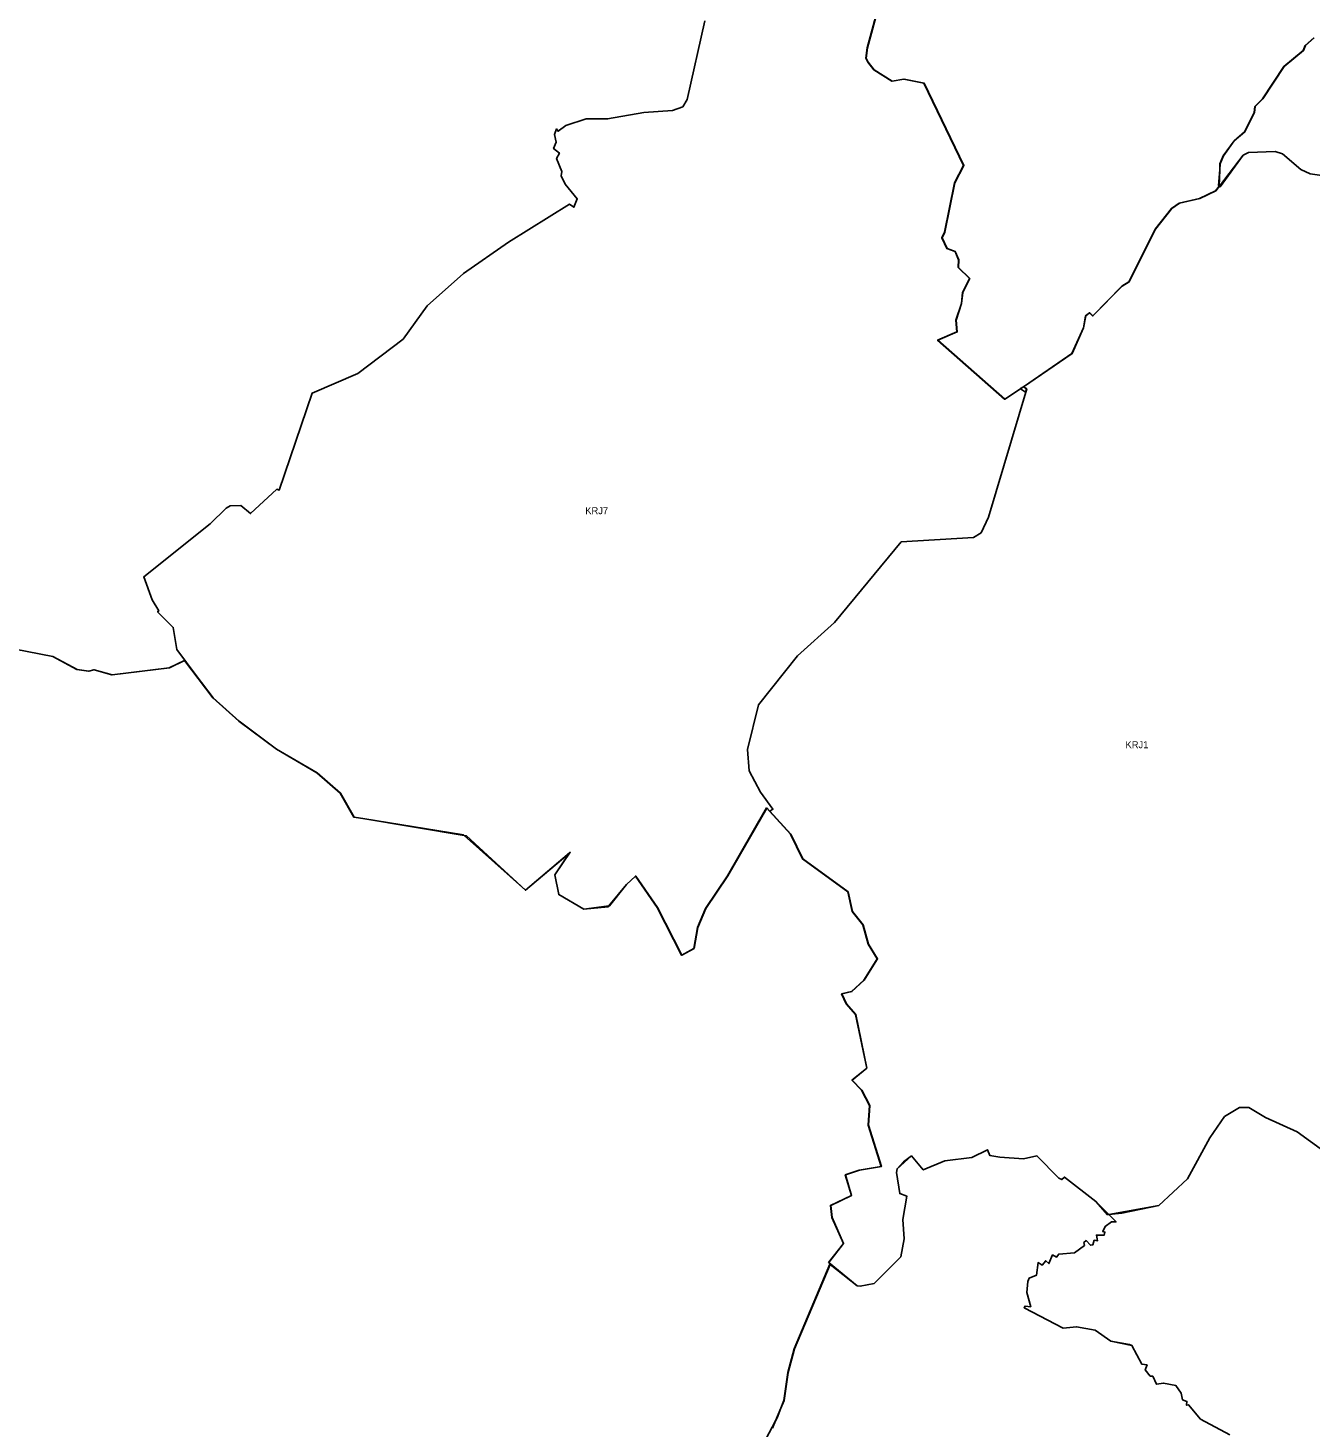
# Model space of a CAD drawing. Extents: x -563112 to -465432, y -1206259 to -1132144.
# Drawn here: x -539574 to -530418, y -1182339 to -1172346 of the extents above; entities that cross this region are included whole.
import ezdxf

# ---------------------------------------------------------------- set-up
doc = ezdxf.new("R2010")
doc.units = 0
doc.layers.add('krajiny', color=7, linetype='Continuous')

msp = doc.modelspace()

# ---------------------------------------------------------------- linework, layer by layer
at = {"layer": 'krajiny'}
for points in [[(-533496.29, -1172164.7), (-533582.38, -1172486.33), (-533593.54, -1172560.47), (-533577.95, -1172590.58), (-533536.6, -1172645.2), (-533407.61, -1172725.48), (-533407.16, -1172725.76), (-533322.96, -1172711.66), (-533321.84, -1172711.47), (-533178.98, -1172738.78), (-532895.06, -1173328.04), (-532960.37, -1173450.05), (-533030.69, -1173803.37), (-533050.53, -1173844.81), (-533015.18, -1173919.49), (-532956.36, -1173940.86), (-532930.99, -1174001.57), (-532934.1, -1174054.49), (-532852.91, -1174134.4), (-532902.3, -1174234.56), (-532911.29, -1174312.58), (-532951.23, -1174431.18), (-532943.05, -1174515.41), (-533080.59, -1174574.89), (-532603.12, -1174994.46), (-532602.21, -1174995.26), (-532490.08, -1174920.45), (-532469.9, -1174906.99), (-532468.82, -1174906.27), (-532446.67, -1174921.9), (-532720.12, -1175837.22), (-532773.04, -1175949.73), (-532825.97, -1175982.82), (-533342.02, -1176013.25), (-533818.38, -1176589.04), (-534083.02, -1176827.29), (-534360.9, -1177178.06), (-534440.29, -1177495.74), (-534427.06, -1177647.95), (-534347.66, -1177800.17), (-534257.89, -1177922.16), (-534280.36, -1177935.65), (-534281.74, -1177936.48), (-534301.94, -1177914.15), (-534303.23, -1177912.72), (-534582.94, -1178397.76), (-534739.65, -1178630.56), (-534797.31, -1178766.3), (-534823.47, -1178916.07), (-534907.83, -1178963.96), (-534909.47, -1178964.89), (-535085.15, -1178623.98), (-535238.69, -1178400.49), (-535239.51, -1178399.3), (-535302.29, -1178458.82), (-535428.49, -1178611.92), (-535433.59, -1178618.1), (-535608.67, -1178636.04), (-535787.02, -1178531.1), (-535815.49, -1178390.49), (-535704.02, -1178229.67), (-535708.88, -1178233.78), (-536024.47, -1178500.17), (-536461.72, -1178110.06), (-536467.3, -1178105.08), (-537185.65, -1177989.67), (-537248.15, -1177979.63), (-537347.39, -1177807.56), (-537512.79, -1177661.96), (-537802.18, -1177493.63), (-538069.5, -1177293.8), (-538256.01, -1177127.53), (-538373.79, -1176968.85), (-538512.44, -1176782.04), (-538538.13, -1176625.03), (-538649.94, -1176512.61), (-538641.29, -1176506.22), (-538689.34, -1176427.85), (-538748.49, -1176262.91), (-538275.3, -1175886.06), (-538159.29, -1175774.39), (-538132.31, -1175757.52), (-538056.31, -1175754.35), (-537986.07, -1175811.81), (-537797.85, -1175638.22), (-537780.87, -1175644.05), (-537545.87, -1174951.77), (-537221.68, -1174812.78), (-536897.5, -1174567.91), (-536725.48, -1174329.65), (-536467.46, -1174098.02), (-536145.91, -1173875.63), (-535709.25, -1173604.28), (-535677.85, -1173625.27), (-535654.14, -1173565.4), (-535740.33, -1173461.12), (-535769.03, -1173401.76), (-535763.8, -1173370.51), (-535802.49, -1173277.42), (-535781.34, -1173238.14), (-535823.23, -1173206.61), (-535804.28, -1173159.88), (-535816.58, -1173105.94), (-535803.59, -1173066.15), (-535790.87, -1173083.11), (-535735.71, -1173041.73), (-535590.16, -1172995.4), (-535437.99, -1172995.4), (-535179.97, -1172949.07), (-534974.87, -1172935.84), (-534902.09, -1172909.36), (-534869.01, -1172856.42), (-534743.31, -1172293.87)], [(-530396.76, -1172416.91), (-530459.25, -1172470.54), (-530473.52, -1172506.43), (-530611.64, -1172619.68), (-530763, -1172850.86), (-530817.71, -1172906.59), (-530823.96, -1172948.13), (-530893.41, -1173086.05), (-530967.3, -1173152.14), (-531043.86, -1173259.18), (-531068.49, -1173315.57), (-531069.56, -1173357.23), (-531072.56, -1173473.8), (-531072.6, -1173475.25), (-531099.02, -1173508.23), (-531213.42, -1173562.4), (-531358.21, -1173595.39), (-531412.88, -1173633.77), (-531529.66, -1173781.62), (-531717.24, -1174158.26), (-531768.67, -1174188.23), (-531975.54, -1174399.98), (-531976.59, -1174401.06), (-531997.91, -1174379.06), (-531998.81, -1174378.13), (-532026.46, -1174399.42), (-532042.56, -1174484.99), (-532124.2, -1174668.52), (-532470.92, -1174906.27), (-532603.12, -1174994.46), (-532604.31, -1174995.26), (-533082.69, -1174574.89), (-532945.15, -1174515.41), (-532953.33, -1174431.18), (-532913.39, -1174312.58), (-532904.4, -1174234.56), (-532855.01, -1174134.4), (-532936.2, -1174054.49), (-532933.09, -1174001.57), (-532958.46, -1173940.86), (-533017.28, -1173919.49), (-533052.63, -1173844.81), (-533032.79, -1173803.37), (-532962.47, -1173450.05), (-532897.16, -1173328.04), (-533181.08, -1172738.78), (-533322.96, -1172711.66), (-533323.94, -1172711.47), (-533407.61, -1172725.48), (-533409.26, -1172725.76), (-533538.7, -1172645.2), (-533580.05, -1172590.58), (-533595.64, -1172560.47), (-533584.48, -1172486.33), (-533498.39, -1172164.7)], [(-534743.31, -1172293.87), (-534869.01, -1172856.42), (-534902.09, -1172909.36), (-534974.87, -1172935.84), (-535179.97, -1172949.07), (-535437.99, -1172995.4), (-535590.16, -1172995.4), (-535735.71, -1173041.73), (-535790.87, -1173083.11), (-535803.59, -1173066.15), (-535816.58, -1173105.94), (-535804.28, -1173159.88), (-535823.23, -1173206.61), (-535781.34, -1173238.14), (-535802.49, -1173277.42), (-535763.8, -1173370.51), (-535769.03, -1173401.76), (-535740.33, -1173461.12), (-535654.14, -1173565.4), (-535677.85, -1173625.27), (-535709.25, -1173604.28), (-536145.91, -1173875.63), (-536467.46, -1174098.02), (-536725.48, -1174329.65), (-536897.5, -1174567.91), (-537221.68, -1174812.78), (-537545.87, -1174951.77), (-537780.87, -1175644.05), (-537797.85, -1175638.22), (-537986.07, -1175811.81), (-538056.31, -1175754.35), (-538132.31, -1175757.52), (-538159.29, -1175774.39), (-538275.3, -1175886.06), (-538748.49, -1176262.91), (-538689.34, -1176427.85), (-538641.29, -1176506.22), (-538649.94, -1176512.61), (-538538.13, -1176625.03), (-538512.44, -1176782.04), (-538373.79, -1176968.85), (-538256.01, -1177127.53), (-538456.81, -1176861.77), (-538457.38, -1176861.02), (-538566.4, -1176913.61), (-538974.53, -1176962.69), (-538976, -1176962.87), (-539103.34, -1176927.89), (-539104.39, -1176927.6), (-539141.5, -1176937.63), (-539142.25, -1176937.83), (-539225.52, -1176925.54), (-539398.31, -1176832.3), (-539764.72, -1176761.4)], [(-530272.31, -1173407.97), (-530423.14, -1173386.86), (-530491, -1173354.76), (-530620.87, -1173244.01), (-530673.46, -1173228.53), (-530863.69, -1173233.82), (-530902.1, -1173253.92), (-531065.26, -1173478.94), (-531071.25, -1173474.72), (-531072.56, -1173473.8), (-531078.14, -1173469.88), (-531069.56, -1173357.23), (-531066.39, -1173315.57), (-531041.76, -1173259.18), (-530965.2, -1173152.14), (-530891.31, -1173086.05), (-530821.86, -1172948.13), (-530815.61, -1172906.59), (-530760.9, -1172850.86), (-530609.54, -1172619.68), (-530471.42, -1172506.43), (-530457.15, -1172470.54), (-530394.66, -1172416.91)], [(-530327.09, -1180362.66), (-530516.91, -1180224.5), (-530743, -1180123.28), (-530862.33, -1180050.34), (-530928.49, -1180050.34), (-531034.34, -1180116.52), (-531140.2, -1180268.74), (-531298.99, -1180559.94), (-531504.08, -1180751.87), (-531768.72, -1180804.82), (-531860.34, -1180815.65), (-531860.43, -1180815.66), (-531869.44, -1180816.73), (-531952.44, -1180723.29), (-532176.3, -1180547.65), (-532197.31, -1180565.38), (-532216.59, -1180554.66), (-532374.07, -1180396.27), (-532468.61, -1180417.07), (-532637.56, -1180405.08), (-532708.93, -1180394.28), (-532725.86, -1180353.27), (-532839.03, -1180409.28), (-533030.29, -1180432.1), (-533185.59, -1180497.42), (-533269.39, -1180397.38), (-533372.51, -1180488.07), (-533376.27, -1180515.8), (-533352.92, -1180665.71), (-533302.29, -1180684.74), (-533329.83, -1180851.46), (-533321.13, -1180989.7), (-533346.22, -1181118.47), (-533535.29, -1181306.76), (-533636.25, -1181325.56), (-533655.99, -1181324.07), (-533855.9, -1181161.17), (-533860.35, -1181157.55), (-533755.43, -1181023.28), (-533837.2, -1180835.67), (-533847.93, -1180749.81), (-533698.5, -1180679.29), (-533742.41, -1180533.05), (-533643.46, -1180497.63), (-533486.1, -1180472.89), (-533579.04, -1180178.48), (-533568.85, -1180036.52), (-533625.06, -1179926.67), (-533694.81, -1179857.46), (-533589.02, -1179769.72), (-533668.89, -1179388.16), (-533735.68, -1179310.71), (-533768.68, -1179240.41), (-533696.19, -1179224.08), (-533608.63, -1179142.07), (-533513.26, -1178990.53), (-533578.18, -1178886.42), (-533616.62, -1178748.47), (-533692.15, -1178653.52), (-533723.36, -1178511.12), (-534047.8, -1178277.04), (-534132.58, -1178101.37), (-534281.74, -1177936.48), (-534280.36, -1177935.65), (-534257.89, -1177922.16), (-534347.66, -1177800.17), (-534427.06, -1177647.95), (-534440.29, -1177495.74), (-534360.9, -1177178.06), (-534083.02, -1176827.29), (-533818.38, -1176589.04), (-533342.02, -1176013.25), (-532825.97, -1175982.82), (-532773.04, -1175949.73), (-532720.12, -1175837.22), (-532446.67, -1174921.9), (-532468.82, -1174906.27), (-532122.1, -1174668.52), (-532040.46, -1174484.99), (-532024.36, -1174399.42), (-531997.91, -1174379.06), (-531996.71, -1174378.13), (-531975.54, -1174399.98), (-531974.49, -1174401.06), (-531766.57, -1174188.23), (-531715.14, -1174158.26), (-531527.56, -1173781.62), (-531410.78, -1173633.77), (-531356.11, -1173595.39), (-531211.32, -1173562.4), (-531096.92, -1173508.23), (-531071.25, -1173474.72), (-530902.1, -1173253.92), (-530863.69, -1173233.82), (-530673.46, -1173228.53), (-530620.87, -1173244.01), (-530491, -1173354.76), (-530423.14, -1173386.86), (-530272.31, -1173407.97)], [(-539764.62, -1176761.01), (-539396.19, -1176832.3), (-539223.4, -1176925.54), (-539141.5, -1176937.63), (-539140.13, -1176937.83), (-539103.34, -1176927.89), (-539102.27, -1176927.6), (-538974.53, -1176962.69), (-538973.88, -1176962.87), (-538564.28, -1176913.61), (-538456.81, -1176861.77), (-538455.26, -1176861.02), (-538373.79, -1176968.85), (-538253.89, -1177127.53), (-538067.38, -1177293.8), (-537800.06, -1177493.63), (-537510.67, -1177661.96), (-537345.27, -1177807.56), (-537246.03, -1177979.63), (-537185.65, -1177989.67), (-536461.72, -1178110.06), (-536444.46, -1178112.93), (-536024.47, -1178500.17), (-535708.22, -1178232.8), (-535708.88, -1178233.78), (-535815.49, -1178390.49), (-535787.02, -1178531.1), (-535608.67, -1178636.04), (-535428.49, -1178611.92), (-535424.26, -1178611.35), (-535302.29, -1178458.82), (-535238.69, -1178400.49), (-535237.39, -1178399.3), (-535083.03, -1178623.98), (-534907.83, -1178963.96), (-534907.35, -1178964.89), (-534821.35, -1178916.07), (-534795.19, -1178766.3), (-534737.53, -1178630.56), (-534580.82, -1178397.76), (-534301.94, -1177914.15), (-534301.11, -1177912.72), (-534280.36, -1177935.65), (-534130.46, -1178101.37), (-534045.68, -1178277.04), (-533721.24, -1178511.12), (-533690.03, -1178653.52), (-533614.5, -1178748.47), (-533576.06, -1178886.42), (-533511.14, -1178990.53), (-533606.51, -1179142.07), (-533694.07, -1179224.08), (-533766.56, -1179240.41), (-533733.56, -1179310.71), (-533666.77, -1179388.16), (-533586.9, -1179769.72), (-533692.69, -1179857.46), (-533622.94, -1179926.67), (-533566.73, -1180036.52), (-533576.92, -1180178.48), (-533483.98, -1180472.89), (-533641.34, -1180497.63), (-533740.29, -1180533.05), (-533696.38, -1180679.29), (-533845.81, -1180749.81), (-533835.08, -1180835.67), (-533753.31, -1181023.28), (-533858.23, -1181157.55), (-533855.9, -1181161.17), (-533850.02, -1181170.33), (-533850.54, -1181171.58), (-534103.2, -1181773.79), (-534149.46, -1181942.87), (-534178.77, -1182141.91), (-534202.01, -1182198.34), (-534239.21, -1182288.71), (-534260.54, -1182340.51)], [(-530998.07, -1182386.92), (-531206.52, -1182277.22), (-531292.02, -1182172.78), (-531305.83, -1182176.6), (-531303.71, -1182149.84), (-531334.4, -1182139.24), (-531343.44, -1182091.42), (-531381.99, -1182035.8), (-531471.03, -1182018.49), (-531521.58, -1182027.08), (-531547.13, -1181969.7), (-531565.47, -1181968.36), (-531600.94, -1181923.93), (-531587.59, -1181888.65), (-531626.11, -1181882.78), (-531695.75, -1181750.79), (-531847, -1181719), (-531958.01, -1181641.18), (-532090.59, -1181616.22), (-532186.28, -1181627.14), (-532465.16, -1181481.07), (-532459, -1181468.57), (-532417.47, -1181473.27), (-532446.55, -1181373.12), (-532438.46, -1181292.59), (-532430.46, -1181269.42), (-532377.75, -1181248.82), (-532365.91, -1181158.04), (-532336.11, -1181175.84), (-532310.7, -1181144.76), (-532288.79, -1181165.42), (-532262.04, -1181103.5), (-532234.24, -1181119.19), (-532217.86, -1181098.27), (-532106.15, -1181087.8), (-532034.91, -1181035.54), (-532038.39, -1181015.15), (-532022.61, -1181001.73), (-531991.06, -1181034.72), (-531973.95, -1181031.5), (-531964.56, -1180998.92), (-531941.03, -1181002.58), (-531948.94, -1180961.87), (-531894.78, -1180963.5), (-531888.48, -1180940.51), (-531903.89, -1180935.42), (-531886.19, -1180899.9), (-531840.89, -1180868.45), (-531808.78, -1180867.52), (-531860.43, -1180815.67), (-531860.34, -1180815.65), (-531504.08, -1180751.87), (-531298.99, -1180559.94), (-531140.2, -1180268.74), (-531034.34, -1180116.52), (-530928.49, -1180050.34), (-530862.33, -1180050.34), (-530743, -1180123.28), (-530516.91, -1180224.5), (-530327.09, -1180362.66)], [(-534308, -1182419.54), (-534239.21, -1182288.71), (-534227.44, -1182266.32), (-534202.01, -1182198.34), (-534180.89, -1182141.91), (-534151.58, -1181942.87), (-534105.32, -1181773.79), (-533852.14, -1181170.33), (-533850.54, -1181171.58), (-533655.99, -1181324.07), (-533636.25, -1181325.56), (-533535.29, -1181306.76), (-533346.22, -1181118.47), (-533321.13, -1180989.7), (-533329.83, -1180851.46), (-533302.29, -1180684.74), (-533352.92, -1180665.71), (-533376.27, -1180515.8), (-533372.51, -1180488.07), (-533326.42, -1180438.59), (-533269.39, -1180397.38), (-533185.59, -1180497.42), (-533030.29, -1180432.1), (-532839.03, -1180409.28), (-532725.86, -1180353.27), (-532708.93, -1180394.28), (-532637.56, -1180405.08), (-532468.61, -1180417.07), (-532374.07, -1180396.27), (-532216.59, -1180554.66), (-532197.31, -1180565.38), (-532176.3, -1180547.65), (-531952.44, -1180723.29), (-531860.43, -1180815.66), (-531808.78, -1180867.52), (-531840.89, -1180868.45), (-531886.19, -1180899.9), (-531903.89, -1180935.42), (-531888.48, -1180940.51), (-531894.78, -1180963.5), (-531948.94, -1180961.87), (-531941.03, -1181002.58), (-531964.56, -1180998.92), (-531973.95, -1181031.5), (-531991.06, -1181034.72), (-532022.61, -1181001.73), (-532038.39, -1181015.15), (-532034.91, -1181035.54), (-532106.15, -1181087.8), (-532217.86, -1181098.27), (-532234.24, -1181119.19), (-532262.04, -1181103.5), (-532288.79, -1181165.42), (-532310.7, -1181144.76), (-532336.11, -1181175.84), (-532365.91, -1181158.04), (-532377.75, -1181248.82), (-532430.46, -1181269.42), (-532438.46, -1181292.59), (-532446.55, -1181373.12), (-532417.47, -1181473.27), (-532459, -1181468.57), (-532465.16, -1181481.07), (-532186.28, -1181627.14), (-532090.59, -1181616.22), (-531958.01, -1181641.18), (-531847, -1181719), (-531713, -1181744), (-531713.14, -1181744.13), (-531695.75, -1181750.79), (-531626.11, -1181882.78), (-531587.59, -1181888.65), (-531600.94, -1181923.93), (-531565.47, -1181968.36), (-531547.13, -1181969.7), (-531521.58, -1182027.08), (-531471.03, -1182018.49), (-531381.99, -1182035.8), (-531343.44, -1182091.42), (-531334.4, -1182139.24), (-531303.71, -1182149.84), (-531305.83, -1182176.6), (-531292.02, -1182172.78), (-531206.52, -1182277.22), (-530998.07, -1182386.92)]]:
    msp.add_lwpolyline(points, dxfattribs=at)
msp.add_lwpolyline([(-532470.92, -1174906.27), (-532469.9, -1174906.99), (-532448.77, -1174921.9), (-532456.03, -1174946.19), (-532490.08, -1174920.45), (-532490.76, -1174919.94)], close=True, dxfattribs=at)

# ---------------------------------------------------------------- texts
for s, p in [('KRJ7', (-535597.58, -1175816.33)), ('KRJ1', (-531741.91, -1177486.66))]:
    msp.add_text(s, height=50, dxfattribs=at).set_placement(p)

doc.saveas('drawing.dxf')
